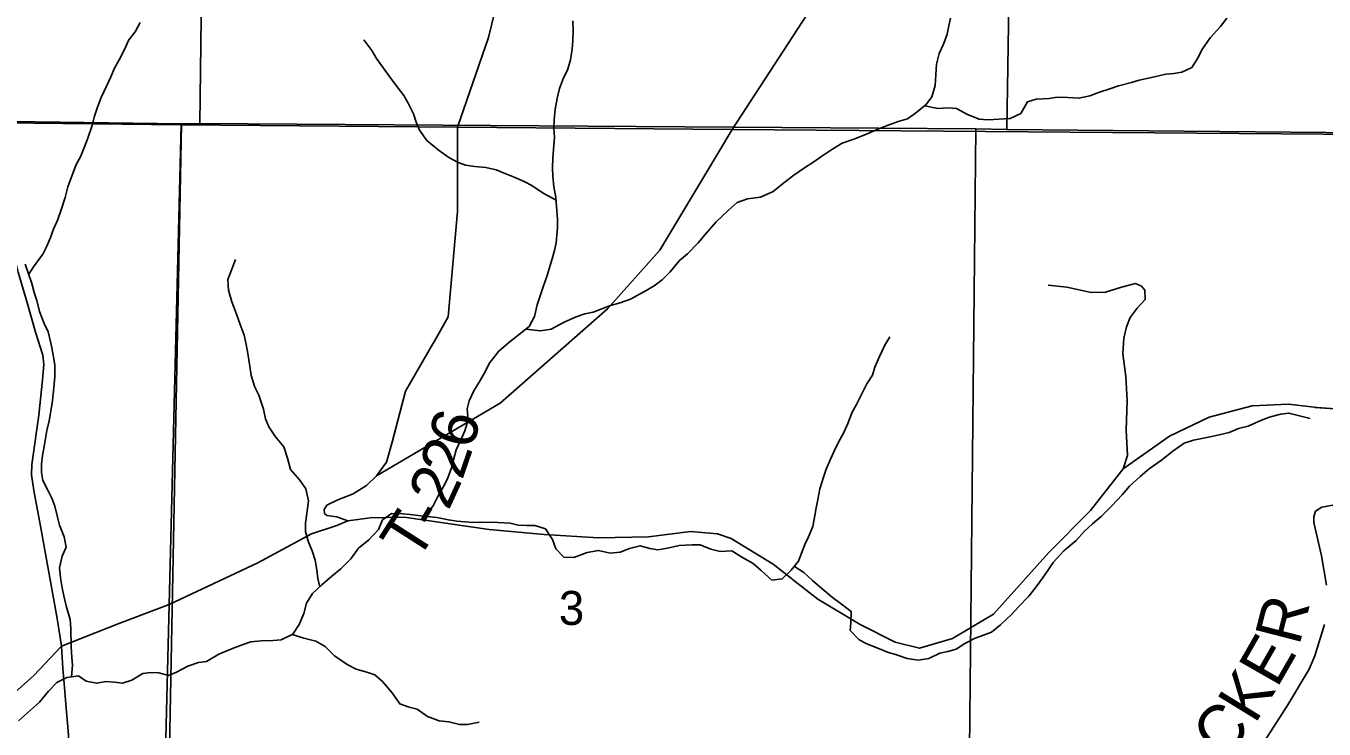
# Model space of a CAD drawing. Extents: x 2043100 to 2470832, y 443715 to 810583.
# Drawn here: x 2274168 to 2282598, y 666337 to 670905 of the extents above; entities that cross this region are included whole.
import ezdxf

# ---------------------------------------------------------------- set-up
doc = ezdxf.new("R2010")
doc.units = 0
for name, color, linetype in [('GM_X_County_Road', 7, 'Continuous'), ('GM_X_Minor_River', 7, 'Continuous'), ('GM_X_Section', 7, 'Continuous'), ('GM_X_Section_Text', 7, 'Continuous'), ('GM_X_State_Route', 7, 'Continuous'), ('GM_X_Township', 7, 'Continuous'), ('GM_X_Township_Road', 7, 'Continuous'), ('GM_X_Township_Road_Text', 7, 'Continuous'), ('GM_X_Township_ROW', 7, 'Continuous')]:
    doc.layers.add(name, color=color, linetype=linetype)

msp = doc.modelspace()

# ---------------------------------------------------------------- linework, layer by layer
at = {"layer": 'GM_X_County_Road'}
for points in [[(2273481.2, 670198.4), (2273499.9, 670153.1), (2273587.9, 669998.2), (2273758, 669858.6), (2273921.9, 669706.7), (2274007, 669609.6), (2274073.8, 669479), (2274118.2, 669305.7), (2274178.4, 669099.2), (2274230.5, 668914.9), (2274276.6, 668766.6), (2274284.6, 668704.4), (2274274.7, 668606.2), (2274250.7, 668375.7), (2274206.8, 668055), (2274202.9, 667988.8), (2274218.9, 667886.6), (2274263.1, 667654.1), (2274369.5, 667054.8), (2274398.8, 666875.7)], [(2274398.8, 666875.7), (2274407.6, 666730), (2274415.7, 666631.8), (2274427.8, 666497.5), (2274441.9, 666325.1), (2274453.9, 666158.7), (2274454, 666078.5), (2274450, 665994.3), (2274422, 665878), (2274404.1, 665775.7), (2274392.1, 665661.4), (2274388.2, 665575.2), (2274412.2, 665499), (2274434.3, 665469), (2274488.3, 665440.9), (2274542.4, 665436.9), (2274588.4, 665451), (2274644.5, 665501.2), (2274742.1, 665646.5), (2274788.5, 665676.3), (2274891.4, 665712.8), (2275063.9, 665756), (2275176.7, 665769.2), (2275201.8, 665764.9)]]:
    msp.add_lwpolyline(points, dxfattribs=at)
at = {"layer": 'GM_X_Minor_River'}
for points in [[(2274185.6, 669292.7), (2274217.3, 669340.4), (2274276.5, 669423.2), (2274303.9, 669473.5), (2274327.3, 669531.8), (2274346.8, 669584.1), (2274374.1, 669648.5), (2274395.5, 669710.8), (2274422.7, 669791.2), (2274439.9, 669859.5), (2274494.4, 670004.2), (2274521.9, 670054.6), (2274547.2, 670120.9), (2274570.6, 670177.2), (2274597.8, 670257.6), (2274611.2, 670311.8), (2274632.6, 670378.1), (2274655.9, 670440.4), (2274691.1, 670514.9), (2274718.5, 670575.3), (2274743.9, 670631.6), (2274773.4, 670686), (2274806.7, 670748.4), (2274836, 670814.8), (2274877.5, 670867.3), (2274908.9, 670927.7)], [(2276762, 667718.8), (2276814.4, 667790.8), (2276843.8, 667847.2), (2276879.1, 667911.7), (2276906.6, 667962), (2276931.8, 668034.4), (2276945.3, 668086.6), (2276962.6, 668150.9), (2276993.9, 668219.3), (2277017.3, 668273.6), (2277040.6, 668346), (2277033.9, 668418), (2277045.3, 668470.2), (2277076.6, 668534.6), (2277118, 668601.1), (2277153.3, 668661.6), (2277176.8, 668711.9), (2277236, 668790.6), (2277301.4, 668847.3), (2277372.8, 668902.1), (2277436.2, 668952.9), (2277471.6, 669017.3), (2277488.8, 669093.6), (2277508.2, 669151.9), (2277525.6, 669204.1), (2277554.7, 669290.5), (2277570.2, 669342.8), (2277585.7, 669393), (2277601.1, 669445.2), (2277610.6, 669495.4), (2277616.1, 669545.5), (2277619.6, 669595.6), (2277619, 669649.7), (2277614.2, 669731.7), (2277609.6, 669789.8), (2277596.9, 669859.7), (2277590.2, 669929.7), (2277587.6, 669983.8), (2277589, 670045.9), (2277596.1, 670130), (2277599.6, 670180.2), (2277597, 670242.2), (2277598.4, 670296.3), (2277605.7, 670364.5), (2277620.9, 670444.7), (2277632.3, 670498.9), (2277659.6, 670567.3), (2277685.1, 670617.6), (2277704.4, 670685.9), (2277715.7, 670754.1), (2277719.1, 670810.2), (2277722.4, 670878.3), (2277719.8, 670938.3)], [(2277415.2, 668936), (2277508.5, 668923.5), (2277578.4, 668934.3), (2277663.9, 668981.2), (2277741.5, 669016), (2277797.3, 669034.7), (2277851.2, 669045.2), (2277908.9, 669067.8), (2277964.7, 669088.4), (2278026.5, 669107.1), (2278094.2, 669129.8), (2278179.7, 669176.7), (2278247.2, 669217.5), (2278298.8, 669256.1), (2278352.3, 669306.7), (2278411.5, 669381.4), (2278463.1, 669423.9), (2278534.3, 669496.8), (2278579.7, 669551.3), (2278650.9, 669632.1), (2278728.1, 669707), (2278787.5, 669757.7), (2278853.3, 669782.4), (2278939.1, 669793.3), (2279020.7, 669830.2), (2279090.1, 669886.9), (2279155.6, 669935.7), (2279223.1, 669984.4), (2279278.7, 670019), (2279342.2, 670063.7), (2279401.8, 670102.4), (2279469.4, 670143.1), (2279545, 670169.9), (2279616.7, 670198.7), (2279696.4, 670231.5), (2279750.1, 670254.1), (2279831.8, 670285), (2279893.6, 670301.6), (2279945.2, 670338.2), (2280014.6, 670395), (2280050.1, 670445.4), (2280073.3, 670517.7), (2280076.6, 670587.8), (2280081.9, 670658), (2280099.2, 670726.2), (2280126.5, 670786.6), (2280149.9, 670852.9), (2280161.3, 670905.1), (2280172.8, 670955.3)], [(2280004.7, 670386.8), (2280090.8, 670369.7), (2280158.8, 670372.4), (2280210.8, 670368.9), (2280279.2, 670331.6), (2280359.4, 670300.4), (2280415.5, 670294.9), (2280559.3, 670304.4), (2280629, 670337.1), (2280672.2, 670411.7), (2280728, 670430.2), (2280811.9, 670433.1), (2280865.8, 670441.7), (2280933.8, 670440.4), (2281005.8, 670435.1), (2281077.6, 670451.8), (2281139.4, 670474.5), (2281207.1, 670497.2), (2281262.9, 670515.8), (2281346.7, 670538.7), (2281398.5, 670553.2), (2281496.3, 670574.2), (2281570, 670591), (2281622, 670595.5), (2281673.9, 670604.1), (2281739.5, 670634.8), (2281780.9, 670699.3), (2281804.3, 670749.5), (2281857.5, 670828.2), (2281924.8, 670901), (2281966.2, 670955.4)], [(2277610.9, 669773.5), (2277527.3, 669818.9), (2277452.9, 669868.3), (2277402.6, 669893.8), (2277338.3, 669923.2), (2277274.1, 669948.5), (2277221.9, 669970), (2277153.7, 669985.4), (2277083.7, 669992.7), (2277021.6, 670000), (2276969.5, 670019.5), (2276915.2, 670051), (2276844.7, 670100.4), (2276772.1, 670161.7), (2276723.4, 670227.3), (2276702.9, 670279.2), (2276684.3, 670335), (2276649.7, 670402.8), (2276621.1, 670454.5), (2276578.6, 670510.2), (2276527.9, 670577.8), (2276489.4, 670631.4), (2276444.7, 670693), (2276414.2, 670744.8), (2276361.5, 670814.4)], [(2274464.3, 666675.1), (2274469.8, 666751.2), (2274465.3, 666801.2), (2274460.6, 666871.3), (2274459.4, 666989.4), (2274454.8, 667047.5), (2274432, 667129.4), (2274413.2, 667203.3), (2274402.7, 667255.3), (2274392, 667319.3), (2274385.4, 667383.3), (2274402.6, 667459.6), (2274428, 667517.9), (2274415.3, 667585.9), (2274386.5, 667661.7), (2274372, 667713.7), (2274355.2, 667785.6), (2274336.7, 667837.5), (2274310.2, 667889.3), (2274277.6, 667951.1), (2274269, 668003), (2274268.5, 668057.1), (2274275.9, 668113.3), (2274285.3, 668173.5), (2274294.8, 668223.6), (2274304.2, 668275.8), (2274319.6, 668340.1), (2274330.8, 668414.3), (2274340.2, 668472.5), (2274349.3, 668554.7), (2274354.6, 668624.8), (2274355.8, 668701), (2274345.1, 668769), (2274332.5, 668834.9), (2274311.6, 668916.8), (2274285.1, 668972.6), (2274256.3, 669050.4), (2274237.6, 669120.3), (2274221, 669174.3), (2274206.4, 669232.2), (2274163.2, 669357.9)], [(2276076.1, 667261.8), (2276063.5, 667314.4), (2276056.9, 667370.4), (2276046.3, 667434.4), (2276025.7, 667494.3), (2276003.1, 667550.2), (2275984.4, 667620.1), (2275983.8, 667674.1), (2275996.8, 667770.4), (2276002.3, 667820.6), (2275985.6, 667896.5), (2275947, 667954.2), (2275886.3, 668023.7), (2275865.5, 668097.6), (2275842.8, 668169.4), (2275788.2, 668235), (2275745.5, 668300.6), (2275723, 668352.5), (2275710.3, 668414.4), (2275679.4, 668506.3), (2275654.9, 668558.1), (2275630.1, 668633.9), (2275619.4, 668707.9), (2275608.6, 668777.9), (2275598.1, 668835.9), (2275585.4, 668895.9), (2275558.7, 668965.7), (2275536.1, 669031.5), (2275505.2, 669113.3), (2275482.5, 669189.2), (2275479.8, 669257.3), (2275505.1, 669325.6), (2275528.4, 669388)], [(2275341.3, 666776.2), (2275420.8, 666823), (2275498.4, 666855.9), (2275572.1, 666884.7), (2275627.9, 666903.3), (2275695.8, 666910), (2275773.7, 666912.8), (2275825.7, 666915.3), (2275901.3, 666952.2), (2275942.6, 667016.7), (2275971.9, 667087.1), (2275989.2, 667155.4), (2276028.5, 667217.9), (2276089.9, 667274.6), (2276153.3, 667329.3), (2276212.8, 667378), (2276278.1, 667442.8), (2276327.4, 667511.4), (2276394.8, 667566.2), (2276458.1, 667632.9), (2276483.5, 667695.3), (2276541, 667737.9), (2276613, 667734.7), (2276663, 667731.2), (2276733.1, 667721.9), (2276837.2, 667710.9), (2276911.3, 667695.7), (2276965.4, 667688.2), (2277045.4, 667681), (2277107.4, 667679.7), (2277183.4, 667680.4), (2277233.4, 667678.9), (2277313.4, 667673.8), (2277365.5, 667662.3), (2277419.5, 667658.8), (2277473.5, 667659.4), (2277541.7, 667638), (2277586.4, 667568.4), (2277609, 667508.5), (2277661.6, 667453), (2277725.5, 667451.6), (2277813.2, 667484.6), (2277887, 667497.3), (2277961.2, 667480.1), (2278027.1, 667486.8), (2278086.8, 667509.4), (2278156.6, 667528.1), (2278218.8, 667510.8), (2278270.8, 667501.3), (2278334.7, 667511.9), (2278410.5, 667528.7), (2278492.4, 667533.6), (2278546.4, 667534.1), (2278614.7, 667504.8), (2278676.8, 667491.4), (2278752.8, 667494.2), (2278821.2, 667450.8), (2278891.6, 667411.5), (2278942, 667367.9), (2279012.6, 667304.5), (2279078.5, 667313.2), (2279137.9, 667369.9), (2279185.3, 667426.5), (2279204.8, 667478.8), (2279226.2, 667535.1), (2279249.7, 667585.4), (2279278.9, 667653.8), (2279292.2, 667724), (2279299.7, 667774.2), (2279311.1, 667828.4), (2279324.4, 667898.6), (2279347.6, 667972.9), (2279365.1, 668025.2), (2279392.4, 668089.6), (2279415.9, 668141.9), (2279445.3, 668200.3), (2279478.6, 668262.7), (2279506, 668323), (2279533.2, 668395.4), (2279560.7, 668445.8), (2279601.9, 668528.3), (2279629.3, 668580.7), (2279664.7, 668635.1), (2279680.2, 668687.3), (2279711.5, 668757.8), (2279744.7, 668830.2), (2279778.1, 668884.6)], [(2279158, 667393.8), (2279220, 667354.7), (2279276.6, 667301.2), (2279339.1, 667247.8), (2279405.6, 667192.4), (2279456, 667154.8), (2279526.5, 667101.4), (2279525.3, 667027.3), (2279519.8, 666977.2), (2279578.4, 666915.7), (2279628.7, 666890.2), (2279711, 666856.9), (2279763.2, 666835.4), (2279821.3, 666818), (2279891.6, 666794.7), (2279961.7, 666783.4), (2280031.5, 666796.1), (2280103.1, 666828.9), (2280155, 666841.4), (2280208.8, 666856), (2280264.4, 666892.6), (2280332, 666927.4), (2280385.8, 666946), (2280437.6, 666966.5), (2280497.1, 667013.2), (2280568.4, 667080), (2280613.9, 667130.6), (2280681.1, 667199.3), (2280722.6, 667251.9), (2280769.9, 667316.4), (2280803.4, 667366.8), (2280838.8, 667419.3), (2280908, 667494.1), (2280987.3, 667561), (2281042.7, 667621.7), (2281094.1, 667670.2), (2281149.7, 667716.9), (2281220.9, 667787.7), (2281286.2, 667858.5), (2281335.6, 667915.1), (2281404.9, 667977.9), (2281462.4, 668028.5), (2281541.8, 668083.4), (2281615.1, 668142.2), (2281690.6, 668195.1), (2281750.3, 668213.7), (2281858.1, 668234.8), (2281917.9, 668247.5), (2281981.7, 668264.1), (2282043.5, 668288.8), (2282105.3, 668305.4), (2282190.9, 668344.4), (2282244.7, 668362.9), (2282316.4, 668383.7), (2282370.3, 668390.2), (2282438.5, 668372.9), (2282508.6, 668355.6)], [(2275896.8, 666950), (2275971.5, 666926.8), (2276049.7, 666907.6), (2276110, 666872.2), (2276170.6, 666812.7), (2276253.2, 666755.5), (2276311.5, 666726), (2276381.7, 666706.7), (2276433.8, 666689.2), (2276484.2, 666645.7), (2276547, 666572.2), (2276595.7, 666500.6), (2276655.9, 666479.1), (2276708, 666465.6), (2276776.5, 666418.3), (2276850.7, 666391), (2276914.8, 666383.6), (2276982.9, 666366.3), (2277034.9, 666366.8), (2277110.8, 666381.6)], [(2274119.7, 666389), (2274177.1, 666441.6), (2274256.4, 666510.6), (2274313.6, 666583.3), (2274369, 666639.9), (2274432.7, 666670.7), (2274508.5, 666681.4), (2274558.9, 666647.9), (2274625, 666634.6), (2274688.8, 666645.2), (2274742.9, 666641.8), (2274794.9, 666634.3), (2274854.7, 666655), (2274926.2, 666697.8), (2274978.1, 666704.3), (2275030.1, 666702.8), (2275094.3, 666685.5), (2275146.1, 666706), (2275219.6, 666744.8), (2275287.4, 666769.6), (2275341.3, 666776.2)]]:
    msp.add_lwpolyline(points, dxfattribs=at)
at = {"layer": 'GM_X_Section'}
for points in [[(2270049.6, 675647.5), (2275364.5, 675592), (2275297.1, 670270.9), (2275177, 670269.5), (2269964, 670340.2)], [(2280621.4, 675535.8), (2280537.8, 670232.5), (2280337.7, 670236.2), (2275297.1, 670270.9), (2275364.5, 675592)], [(2280621.4, 675535.8), (2285935, 675492.2), (2285836.8, 670182.6), (2280537.8, 670232.5)], [(2269547.7, 670345.3), (2269964, 670340.2), (2275177, 670269.5), (2275075.3, 664974), (2269488.3, 665022.3)], [(2275177, 670269.5), (2275297.1, 670270.9), (2280337.7, 670236.2), (2280282.1, 664929.2), (2275075.3, 664974)], [(2280537.8, 670232.5), (2285836.8, 670182.6), (2285762.8, 664857.2), (2280282.1, 664929.2), (2280337.7, 670236.2)]]:
    msp.add_lwpolyline(points, close=True, dxfattribs=at)
at = {"layer": 'GM_X_State_Route'}
for points in [[(2279144.7, 667311.4), (2279310.9, 667180.8), (2279586, 667016.5), (2279812.3, 666901.7), (2279971.3, 666862), (2280184.9, 666925.5), (2280451.2, 667082.1), (2280810, 667484.8), (2281080.6, 667757.8), (2281293.4, 668028.3), (2281594.5, 668240.3), (2281852.2, 668363), (2282130.3, 668437.7), (2282366.8, 668447.8), (2282553.5, 668425.4), (2282760.1, 668411.2), (2282539.9, 668425.3), (2282920.4, 668401.4)], [(2274073.3, 666555.6), (2274219.7, 666684.3), (2274398.8, 666875.7), (2274776.7, 667024.8), (2275098.7, 667146.3), (2275673.1, 667416.8), (2276022.5, 667605.2), (2276186.6, 667659.9), (2276259.2, 667689.7), (2276402.3, 667708.5), (2276624.1, 667714.5), (2277176.8, 667633.1), (2277534.1, 667600.5), (2277885.3, 667579.9), (2278210.1, 667584.9), (2278484.2, 667619.3), (2278658.9, 667605.9), (2278747.5, 667575.2), (2279020.7, 667408.9), (2279140.5, 667314.8), (2279144.7, 667311.4)]]:
    msp.add_lwpolyline(points, dxfattribs=at)
at = {"layer": 'GM_X_Township'}
for points in [[(2291206.9, 678354.6), (2291162.8, 672835.5), (2291164.8, 670135.2), (2290748.7, 670138.4), (2290332.7, 670141.7), (2286978.2, 670168), (2282870.2, 670200.2), (2278754.8, 670232.4), (2276970, 670247.6), (2275176.6, 670262.9), (2273446.7, 670282.5), (2271780.8, 670301.7), (2269658, 670368), (2268643.4, 670380.1), (2262116.1, 670457.7), (2260331.7, 670478.9), (2258672.2, 670481.8), (2258742.3, 671669), (2258825.8, 676651)], [(2274821.9, 657525.7), (2275019.2, 663966.2), (2275063.9, 665756), (2275098.7, 667146.3), (2275176.6, 670262.9), (2276970, 670247.6), (2278754.8, 670232.4), (2282870.2, 670200.2), (2286978.2, 670168), (2290332.7, 670141.7), (2290748.7, 670138.4), (2291164.8, 670135.2), (2291162.8, 672835.5), (2291206.9, 678354.6)], [(2273446.7, 670282.5), (2275176.6, 670262.9), (2275098.7, 667146.3), (2275063.9, 665756), (2275019.2, 663966.2), (2274821.9, 657525.7), (2274766.7, 654861.3), (2274647.3, 649091.5), (2274633.2, 646890.2), (2274616.1, 644239.2), (2274597.2, 643765.8), (2273849.4, 643774.3)]]:
    msp.add_lwpolyline(points, dxfattribs=at)
at = {"layer": 'GM_X_Township_Road'}
for points in [[(2281293.4, 668028.3), (2281321.8, 668114), (2281312.6, 668278.3), (2281319.2, 668470.8), (2281310.1, 668627.1), (2281291, 668775.3), (2281298.2, 668877.5), (2281315.7, 668949.8), (2281339.3, 669010.1), (2281385, 669070.5), (2281436.6, 669127), (2281434.2, 669189.1), (2281412, 669215), (2281373.8, 669232.8), (2281283.8, 669208.1), (2281177.9, 669175.3), (2281085.8, 669172.7), (2280927.3, 669207.6), (2280807, 669220.8)], [(2276259.2, 667689.7), (2276187.1, 667714.8), (2276122.9, 667724.4), (2276106.8, 667738.3), (2276104.6, 667762.3), (2276122.5, 667790.5), (2276194.3, 667825.1), (2276292.2, 667865.9), (2276379.9, 667918.6), (2276444.9, 667981.3), (2276509, 668069.9), (2276546.1, 668200.5), (2276631.9, 668531.8), (2276809.3, 668839.2), (2276820.1, 668857.9)], [(2282614.5, 667270.8), (2282582.4, 667463.2), (2282532.2, 667679.7), (2282532.2, 667715.7), (2282542.2, 667751.8), (2282584.3, 667777.9), (2282736.4, 667806)], [(2282138.5, 666142), (2282362.6, 666492.9), (2282500.6, 666725.5), (2282538.6, 666811.7), (2282600.6, 667016.2)]]:
    msp.add_lwpolyline(points, dxfattribs=at)
at = {"layer": 'GM_X_Township_ROW'}
for points in [[(2276970.3, 670248.5), (2277172.1, 670830.5), (2277281, 671276.2), (2277303.8, 671729.2), (2277205.6, 672285.6), (2277092.5, 672693.6), (2277057.6, 672823.6), (2277022.3, 672991.7), (2276937.4, 673373.9), (2276906.2, 673530), (2276850.9, 673703.9), (2276744.7, 673991.7), (2276662.7, 674249.6), (2276621.6, 674393.6), (2276621.6, 674672.2), (2276631.8, 674924.7), (2276590.4, 675210.1)], [(2281006.2, 673761.1), (2280737.5, 673339), (2280462.5, 672937.2), (2279976.1, 672027.9), (2279426.1, 671266.6), (2278754.8, 670232.4), (2278667.2, 670086.5)], [(2276820.1, 668857.9), (2276910.8, 669014.8), (2276969.9, 669700.7), (2276970, 670247.6), (2276970.3, 670248.5)], [(2278667.2, 670086.5), (2278283.9, 669447.7), (2277945.5, 669066.9), (2277247.5, 668453.5), (2276444.9, 667981.3)]]:
    msp.add_lwpolyline(points, dxfattribs=at)

# ---------------------------------------------------------------- texts
at = {"layer": 'GM_X_Section_Text'}
msp.add_text('3', height=220.8, rotation=0.00001, dxfattribs=at).set_placement((2277629, 667013.1))
at = {"layer": 'GM_X_Township_Road_Text'}
for s, rotation, p in [('6', 74.97639, (2277066.9, 668144.9)), ('2', 71.04616, (2277000.3, 667948.6)), ('2', 65.46542, (2276911.8, 667750.9)), ('T', 57.37859, (2276706.8, 667414.9)), ('-', 59.82128, (2276835, 667615.8)), ('R', 75.59564, (2282436.9, 666873.3)), ('E', 60.18866, (2282292.3, 666597.3)), ('K', 58.47863, (2282149.3, 666363.8)), ('C', 45.60204, (2281931.7, 666129.8))]:
    msp.add_text(s, height=300, rotation=rotation, dxfattribs=at).set_placement(p)

doc.saveas('drawing.dxf')
